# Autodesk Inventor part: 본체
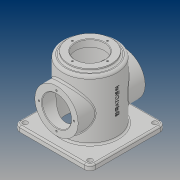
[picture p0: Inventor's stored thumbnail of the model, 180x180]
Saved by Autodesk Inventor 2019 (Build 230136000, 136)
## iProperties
Created: 2019-03
Part Number: 본체
Material: 일반
Document SubType Name: Modeling
Designer: PC312-20
Density: 1 g/cm^3
Appearance: 기본값
Author: PC312-20
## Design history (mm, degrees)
sketch "스케치1"
  geometry: L1 (0, 0)-(0, 125); L2 (-27, 125)-(-40, 125); L3 (-40, 125)-(-40, 120); L4 (-40, 120)-(-50, 120); L5 (-50, 120)-(-50, 0); L6 (-27, 125)-(-27, 112); L7 (-27, 112)-(-45, 112); L8 (-45, 112)-(-45, 0); L9 (-45, 0)-(-50, 0)
  constraints: 18 end point, 5 vertical, 4 horizontal, 1 point on line
  dimensions: "d1" = 125 distance of L1.start L1.end; "d2" = 54 diameter of L6 L1; "d3" = 80 diameter of L3 L1; "d4" = 100 diameter of L5 L1; "d5" = 13 distance between parallel lines of L7 L2; "d6" = 112 distance between parallel lines of L9 L7; "d7" = 120 distance between parallel lines of L9 L4; "d8" = 90 diameter of L8 L1
revolve "회전1" sketch "스케치1" stored, may be unused: angle "d9" = 90 deg
sketch "스케치2"
  geometry: L1 (70, 70)-(-70, 70); L2 (-70, 70)-(-70, -70); L3 (-70, -70)-(70, -70); L4 (70, -70)-(70, 70); L5 (70, 70)-(-70, -70); L6 (-70, 70)-(70, -70); 2 further points
  constraints: 12 end point, 2 midpoint, 2 parallel, 1 horizontal, 1 perpendicular
  dimensions: "d10" = 140 distance of L3.end L2.end; "d11" = 140 distance of L2.end L1.end
extrude "돌출1" join sketch "스케치2" distance "d12" = 10; taper "d13" = 0 deg
sketch "스케치3"
  geometry: C1 r 45 at (70, -70); 1 further point
  constraints: 1 centre point, 1 coincident
  dimensions: "d14" = 90 diameter of C1
extrude "돌출2" cut sketch "스케치3" distance "d15" = 10; taper "d16" = 0 deg
node "작업 평면1"
sketch "스케치4"
  geometry: L1 (-70, 0)-(70, 0) reference; C1 r 40 at (0, 60); 2 further points
  constraints: 1 centre point, 1 midpoint, 1 vertical alignment
  dimensions: "d18" = 80 diameter of C1; "d19" = 60 distance from line of L1 C1.centre
extrude "돌출3" join sketch "스케치4" stored distance "d20" = 10; taper "d21" = 0 deg
sketch "스케치5"
  geometry: C1 r 40 at (0, 0) reference; 2 further points
  constraints: 1 vertical alignment
  dimensions: "d22" = 32.5 distance of C1.centre point (0, 32.5)
hole "구멍1" sketch "스케치5" at (0, 32.5) diameter "d23" = 3.242; stored, may be unused: countersink angle "d27" = 90 deg, drill point angle "d29" = 118 deg; dims "d24" = 8, "d25" = 4, "d26" = 2, "d28" = 10
sketch "스케치6"
  geometry: C1 r 40 at (0, 0) reference; C2 r 27 at (0, 0); 1 further point
  constraints: 1 centre point, 1 coincident
  dimensions: "d33" = 54 diameter of C2
extrude "돌출4" cut sketch "스케치6" extent not by distance; stored distance "d34" = 10; taper "d35" = 0 deg
sketch "스케치7"
  geometry: 2 further points
  constraints: 1 vertical alignment
  dimensions: "d36" = 32.5 distance of point (0, 0) point (0, 32.5)
hole "구멍2" sketch "스케치7" at (0, 32.5) diameter "d37" = 3.242; stored, may be unused: countersink angle "d41" = 90 deg, drill point angle "d43" = 118 deg; dims "d38" = 8, "d39" = 4, "d40" = 2, "d42" = 10
fillet "모깎기1" dims "d47" = 10
sketch "스케치8"
  geometry: A1 r 10 centre (60, -60) between (60, -70) and (70, -60) reference; A2 r 10 centre (60, 60) between (70, 60) and (60, 70) reference; A3 r 10 centre (-60, -60) between (-70, -60) and (-60, -70) reference; A4 r 10 centre (-60, 60) between (-60, 70) and (-70, 60) reference; 5 further points
  constraints: 4 coincident
hole "구멍3" sketch "스케치8" at (60, -60), (60, 60), (-60, -60), (-60, 60) diameter "d48" = 9; stored, may be unused: countersink angle "d52" = 90 deg, drill point angle "d54" = 118 deg; dims "d49" = 8, "d50" = 4, "d51" = 2, "d53" = 10
fillet "모깎기2" dims "d55" = 5
fillet "모깎기3" dims "d56" = 3
fillet "모깎기4" dims "d57" = 3
fillet "모깎기5" dims "d58" = 3
fillet "모깎기6" dims "d59" = 3
fillet "모깎기7" dims "d60" = 3
chamfer "모따기1" distance "d61" = 1; stored, may be unused: second distance "d62" = 2, angle "d63" = 45 deg
node "작업 평면2"
sketch "스케치9"
  geometry: L1 (0, 60)-(0, -60) reference; 2 further points
  constraints: 1 horizontal alignment, 1 other
  dimensions: "d65" = 70 distance from line of L1 point (70, 0)
feature "엠보싱1" sketch "스케치9" dims "d1" = 125, "d2" = 54, "d3" = 80, "d4" = 100, "d5" = 13, "d6" = 112, "d7" = 120, "d8" = 90, "d66" = 0.5, "d67" = 0
node "솔리드1"
pattern_circular "원형 패턴1" dims angle "d31" = 360 deg
mirror "미러1"
pattern_circular "원형 패턴2" dims angle "d45" = 360 deg
other parameters: "d17" = 62, "d64" = 117.5
